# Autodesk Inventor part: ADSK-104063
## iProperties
Shininess: 0.0
Created: 2001-01
Part Number: ADSK-104063
Document SubType Name: Modeling
Stock Number: ADSK-104063
Density: 1 g/cm^3
Density: 0.0
Volumn: 0.0
Area: 0.0
PropertySet Name: Model Information
Control State: 0
Master: False
Checked Out: False
Author: gao
